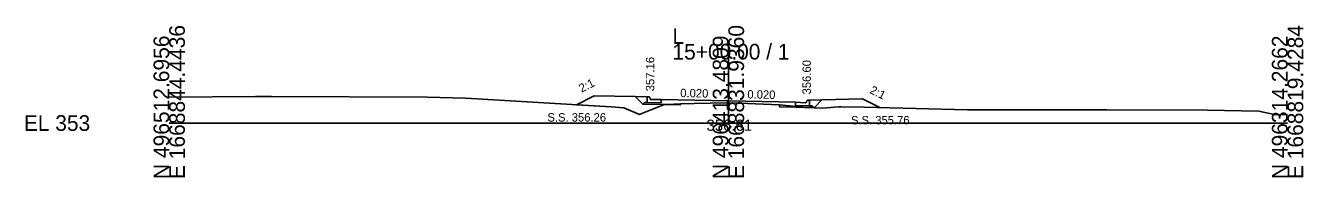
# Model space of a CAD drawing. Extents: x -26 to 203, y -10 to 5517.
# Drawn here: x -25.7 to 202.8, y 4990.3 to 5017.4 of the extents above; entities that cross this region are included whole.
import ezdxf

# ---------------------------------------------------------------- set-up
doc = ezdxf.new("R2010")
doc.units = 0
for name, color, linetype in [('Exist Cross Section Cell', 7, 'Continuous'), ('Exist XS Center Line Elevation Label', 7, 'Continuous'), ('Exist XS Ground Line', 7, 'Continuous'), ('Prop XS Earthwork Shape', 7, 'Continuous'), ('Prop XS Finish Grade', 7, 'Continuous'), ('Prop XS Finish Grade CurbGutter', 7, 'Continuous'), ('Prop XS Finish Grade Earthwork', 7, 'Continuous'), ('Prop XS Finish Grade Pavement', 7, 'Continuous'), ('Prop XS Geopak Shape', 7, 'Continuous'), ('Prop XS Hydro Elevations', 7, 'Continuous'), ('Prop XS Pvmt Edge Slope', 7, 'Continuous'), ('Prop XS SE Text', 7, 'Continuous'), ('Prop XS Side Slope Text', 7, 'Continuous'), ('Prop XS SS Elevation Text', 7, 'Continuous'), ('Prop XS Subgrade CurbGutter', 7, 'Continuous'), ('Prop XS Subgrade Earthwork', 7, 'Continuous')]:
    doc.layers.add(name, color=color, linetype=linetype)

msp = doc.modelspace()

# ---------------------------------------------------------------- linework, layer by layer
at = {"layer": 'Exist Cross Section Cell'}
for p, q in [((100, 5000), (100, 5014.12)), ((0, 5000), (100, 5000)), ((100, 5000), (200, 5000))]:
    msp.add_line(p, q, dxfattribs=at)
at = {"layer": 'Exist XS Ground Line'}
for p, q in [((0, 5004.63), (15.42, 5004.71)), ((15.42, 5004.71), (18.29, 5004.71)), ((18.29, 5004.71), (46.1, 5004.64)), ((46.1, 5004.64), (52.98, 5004.45)), ((52.98, 5004.45), (79.05, 5002.89)), ((79.05, 5002.89), (81.28, 5002.71)), ((81.28, 5002.71), (84.11, 5001.54)), ((84.54, 5001.72), (88.41, 5003.27)), ((88.41, 5003.27), (89.17, 5003.31)), ((89.17, 5003.31), (91.41, 5003.43)), ((91.41, 5003.43), (93.9, 5003.48)), ((93.9, 5003.48), (99.75, 5003.62)), ((99.75, 5003.62), (103.4, 5003.48)), ((103.4, 5003.48), (109.14, 5003.24)), ((109.14, 5003.24), (113.85, 5002.8)), ((113.85, 5002.8), (116.91, 5002.66)), ((116.91, 5002.66), (119.68, 5002.89)), ((119.68, 5002.89), (120.17, 5002.91)), ((120.17, 5002.91), (124.26, 5002.83)), ((124.26, 5002.83), (142.77, 5002.34)), ((84.11, 5001.54), (84.54, 5001.72)), ((142.77, 5002.34), (167.66, 5002.35)), ((167.66, 5002.35), (185.71, 5002.32)), ((185.71, 5002.32), (194.86, 5002.12)), ((194.86, 5002.12), (197.6, 5001.52)), ((197.6, 5001.52), (200, 5001.44))]:
    msp.add_line(p, q, dxfattribs=at)
at = {"layer": 'Prop XS Earthwork Shape'}
for points in [[(72.81, 5003.26), (79.05, 5002.89), (81.28, 5002.71), (84.11, 5001.54), (84.54, 5001.72), (88.41, 5003.27), (88.6, 5003.28), (88, 5003.29), (84.67, 5003.36), (83.31, 5004.71), (76, 5004.86)], [(88.6, 5003.28), (89.17, 5003.31), (91.41, 5003.43), (91.41, 5003.22)], [(109.14, 5003.24), (109.14, 5002.86), (112, 5002.81), (115.08, 5002.75), (113.85, 5002.8)], [(115.33, 5002.74), (116.91, 5002.66), (119.68, 5002.89), (120.17, 5002.91), (124.26, 5002.83), (127.09, 5002.76), (124, 5004.3), (116.74, 5004.15)]]:
    msp.add_lwpolyline(points, close=True, dxfattribs=at)
at = {"layer": 'Prop XS Finish Grade'}
for p, q in [((85.5, 5004.66), (83.31, 5004.71)), ((114.5, 5004.1), (116.74, 5004.15))]:
    msp.add_line(p, q, dxfattribs=at)
at = {"layer": 'Prop XS Finish Grade CurbGutter'}
for p, q in [((85.5, 5004.66), (85.75, 5004.66)), ((85.75, 5004.66), (85.88, 5004.62)), ((85.97, 5004.53), (85.88, 5004.62)), ((86.03, 5004.28), (85.97, 5004.53)), ((86.13, 5004.19), (86.03, 5004.28)), ((86.25, 5004.17), (86.13, 5004.19)), ((88, 5004.2), (86.25, 5004.17)), ((112, 5003.72), (113.75, 5003.62)), ((113.75, 5003.62), (113.87, 5003.64)), ((113.87, 5003.64), (113.97, 5003.73)), ((113.97, 5003.73), (114.03, 5003.98)), ((114.03, 5003.98), (114.12, 5004.07)), ((114.25, 5004.1), (114.12, 5004.07)), ((114.5, 5004.1), (114.25, 5004.1))]:
    msp.add_line(p, q, dxfattribs=at)
at = {"layer": 'Prop XS Finish Grade Earthwork'}
for p, q in [((76, 5004.86), (72.81, 5003.26)), ((83.31, 5004.71), (76, 5004.86)), ((116.74, 5004.15), (124, 5004.3)), ((124, 5004.3), (127.09, 5002.76))]:
    msp.add_line(p, q, dxfattribs=at)
at = {"layer": 'Prop XS Finish Grade Pavement'}
for p, q in [((88, 5004.2), (100, 5003.96)), ((100, 5003.96), (112, 5003.72))]:
    msp.add_line(p, q, dxfattribs=at)
at = {"layer": 'Prop XS Geopak Shape'}
msp.add_lwpolyline([(76, 5004.86), (72.81, 5003.26), (79.05, 5002.89), (81.28, 5002.71), (84.11, 5001.54), (84.54, 5001.72), (88.41, 5003.27), (89.17, 5003.31), (91.41, 5003.43), (93.9, 5003.48), (99.75, 5003.62), (103.4, 5003.48), (109.14, 5003.24), (113.85, 5002.8), (116.91, 5002.66), (119.68, 5002.89), (120.17, 5002.91), (124.26, 5002.83), (127.09, 5002.76), (124, 5004.3), (116.74, 5004.15), (114.5, 5004.1), (114.25, 5004.1), (114.12, 5004.07), (114.03, 5003.98), (113.97, 5003.73), (113.87, 5003.64), (113.75, 5003.62), (112, 5003.72), (100, 5003.96), (88, 5004.2), (86.25, 5004.17), (86.13, 5004.19), (86.03, 5004.28), (85.97, 5004.53), (85.88, 5004.62), (85.75, 5004.66), (85.5, 5004.66), (83.31, 5004.71)], close=True, dxfattribs=at)
at = {"layer": 'Prop XS Pvmt Edge Slope'}
for p, q in [((85, 5003.68), (84.67, 5003.36)), ((85.5, 5003.67), (85, 5003.68)), ((114.5, 5003.09), (115, 5003.08)), ((115, 5003.08), (115.33, 5002.74))]:
    msp.add_line(p, q, dxfattribs=at)
at = {"layer": 'Prop XS Subgrade CurbGutter'}
for p, q in [((85.5, 5003.67), (85.5, 5004.66)), ((88, 5003.62), (85.5, 5003.67)), ((88, 5004.2), (88, 5003.62)), ((112, 5003.72), (112, 5003.14)), ((112, 5003.14), (114.5, 5003.09)), ((114.5, 5003.09), (114.5, 5004.1))]:
    msp.add_line(p, q, dxfattribs=at)
at = {"layer": 'Prop XS Subgrade Earthwork'}
for p, q in [((84.67, 5003.36), (83.31, 5004.71)), ((88, 5003.29), (84.67, 5003.36)), ((88, 5003.29), (88, 5003.29)), ((91.41, 5003.22), (88, 5003.29)), ((91.41, 5003.22), (91.41, 5003.43)), ((109.14, 5003.24), (109.14, 5002.86)), ((112, 5002.81), (109.14, 5002.86)), ((112, 5002.81), (112, 5002.81)), ((112, 5002.81), (115.33, 5002.74)), ((115.33, 5002.74), (116.74, 5004.15))]:
    msp.add_line(p, q, dxfattribs=at)

# ---------------------------------------------------------------- texts
at = {"layer": 'Exist Cross Section Cell'}
for s, p in [('E 1668844.4436', (2.8, 4990)), ('E 1668831.9360', (102.8, 4990)), ('E 1668819.4284', (202.8, 4990)), ('N 496512.6956', (0, 4990)), ('N 496413.4809', (100, 4990)), ('N 496314.2662', (200, 4990))]:
    msp.add_text(s, height=2.8, rotation=90, dxfattribs=at).set_placement(p)
for s, p in [('L', (90, 5014.12)), ('15+00.00 / 1', (90, 5011.32)), ('EL 353', (-26, 4998.6))]:
    msp.add_text(s, height=2.8, dxfattribs=at).set_placement(p)
at = {"layer": 'Exist XS Center Line Elevation Label'}
msp.add_text('356.61', height=2, dxfattribs=at).set_placement((96.08, 4998.61))
at = {"layer": 'Prop XS Hydro Elevations'}
for s, p in [('357.16', (86.75, 5005.66)), ('356.60', (114.75, 5005.1))]:
    msp.add_text(s, height=1.5, rotation=90, dxfattribs=at).set_placement(p)
at = {"layer": 'Prop XS SE Text'}
for p in [(91.38, 5004.63), (103.38, 5004.39)]:
    msp.add_text('0.020', height=1.5, rotation=358.8542, dxfattribs=at).set_placement(p)
at = {"layer": 'Prop XS Side Slope Text'}
for rotation, p in [(26.5651, (73.73, 5005.41)), (333.4349, (125.15, 5005.4))]:
    msp.add_text('2:1', height=1.5, rotation=rotation, dxfattribs=at).set_placement(p)
at = {"layer": 'Prop XS SS Elevation Text'}
for s, p in [('S.S. 356.26', (67.64, 5000.26)), ('S.S. 355.76', (121.92, 4999.76))]:
    msp.add_text(s, height=1.5, dxfattribs=at).set_placement(p)

doc.saveas('drawing.dxf')
